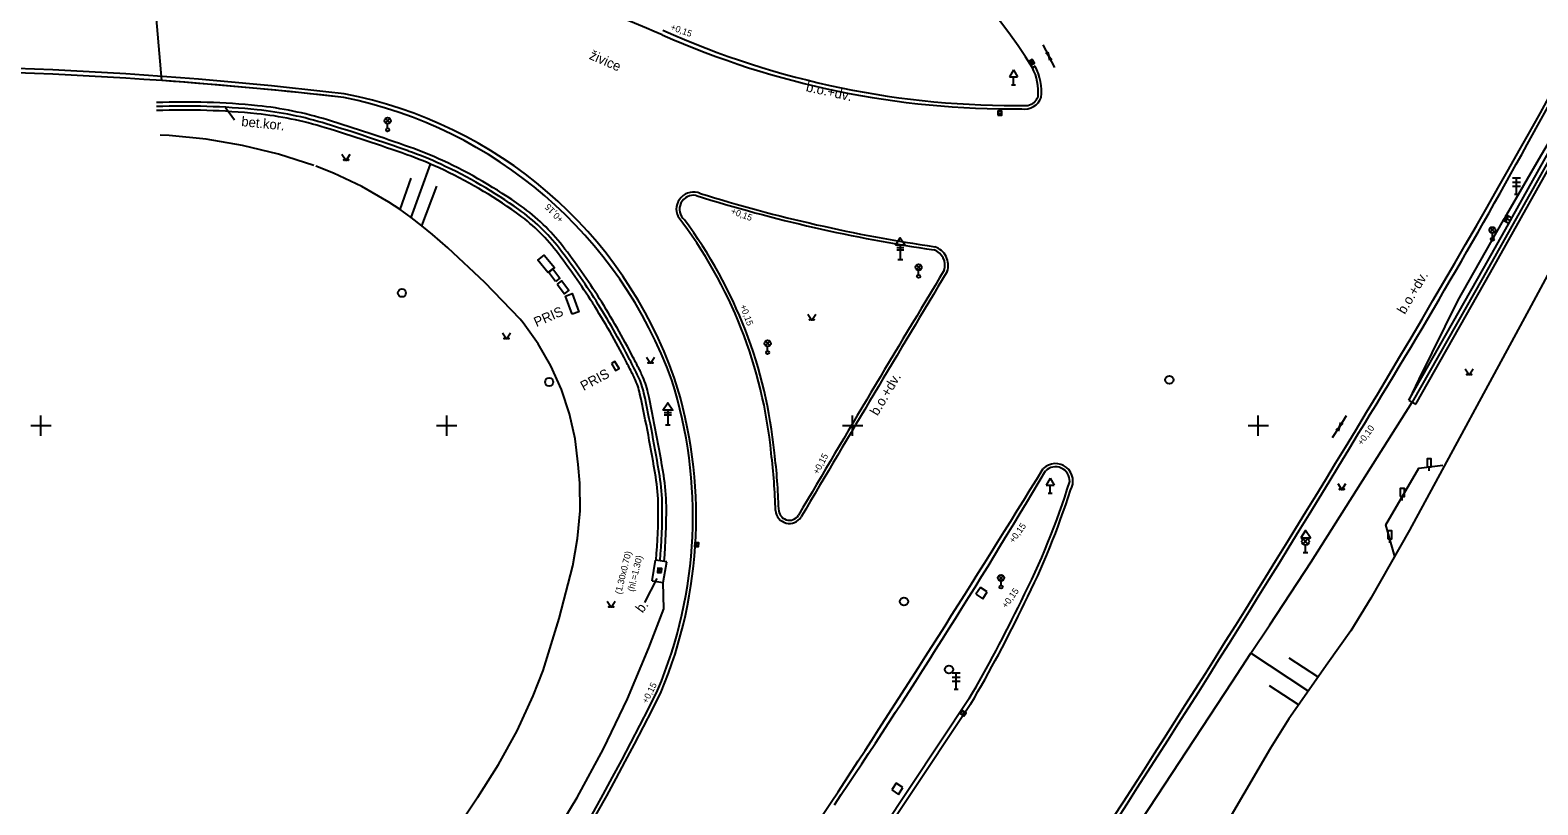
# Model space of a CAD drawing. Extents: x -599151 to -598424, y -1163476 to -1161924.
# Drawn here: x -598975.7 to -598882.8, y -1163223.4 to -1163175.6 of the extents above; entities that cross this region are included whole.
import ezdxf

# ---------------------------------------------------------------- set-up
doc = ezdxf.new("R2010")
doc.units = 0
for name, color, linetype in [('Vrstva 14', 7, 'Continuous'), ('Vrstva 15', 7, 'Continuous'), ('Vrstva 19', 7, 'Continuous'), ('Vrstva 23', 7, 'Continuous'), ('Vrstva 25', 7, 'Continuous'), ('Vrstva 29', 7, 'Continuous'), ('Vrstva 41', 7, 'Continuous'), ('Vrstva 44', 7, 'Continuous'), ('Vrstva 49', 7, 'Continuous'), ('Vrstva 50', 7, 'Continuous'), ('Vrstva 62', 7, 'Continuous'), ('Vrstva 63', 7, 'Continuous'), ('Vrstva 7', 7, 'Continuous')]:
    doc.layers.add(name, color=color, linetype=linetype)

msp = doc.modelspace()

# ---------------------------------------------------------------- linework, layer by layer
at = {"layer": 'Vrstva 14'}
for points in [[(-598956.452, -1163183.287), (-598956.202, -1163183.662), (-598955.952, -1163183.287)], [(-598927.763, -1163193.13), (-598927.513, -1163193.505), (-598927.263, -1163193.13)], [(-598946.569, -1163194.283), (-598946.319, -1163194.658), (-598946.069, -1163194.283)], [(-598937.693, -1163195.792), (-598937.443, -1163196.167), (-598937.193, -1163195.792)], [(-598887.257, -1163196.503), (-598887.007, -1163196.878), (-598886.757, -1163196.503)], [(-598895.103, -1163203.577), (-598894.853, -1163203.952), (-598894.603, -1163203.577)], [(-598940.125, -1163210.824), (-598939.875, -1163211.199), (-598939.625, -1163210.824)]]:
    msp.add_lwpolyline(points, dxfattribs=at)
for centre in [(-598956.327, -1163183.637), (-598956.077, -1163183.637), (-598927.638, -1163193.48), (-598927.388, -1163193.48), (-598946.444, -1163194.633), (-598946.194, -1163194.633), (-598937.568, -1163196.142), (-598937.318, -1163196.142), (-598887.132, -1163196.853), (-598886.882, -1163196.853), (-598894.978, -1163203.927), (-598894.728, -1163203.927), (-598940, -1163211.174), (-598939.75, -1163211.174)]:
    msp.add_circle(centre, 0.025, dxfattribs=at)
at = {"layer": 'Vrstva 15'}
for p, q in [((-598889.482, -1163202.799), (-598889.482, -1163202.549)), ((-598891.13, -1163204.621), (-598891.13, -1163204.371)), ((-598891.906, -1163207.233), (-598891.906, -1163206.983))]:
    msp.add_line(p, q, dxfattribs=at)
for points in [[(-598889.607, -1163202.549), (-598889.357, -1163202.549), (-598889.357, -1163202.049), (-598889.607, -1163202.049)], [(-598891.255, -1163204.371), (-598891.005, -1163204.371), (-598891.005, -1163203.871), (-598891.255, -1163203.871)], [(-598892.031, -1163206.983), (-598891.781, -1163206.983), (-598891.781, -1163206.483), (-598892.031, -1163206.483)]]:
    msp.add_lwpolyline(points, close=True, dxfattribs=at)
at = {"layer": 'Vrstva 19'}
for p, q in [((-598915.08, -1163178.077), (-598915.33, -1163178.51)), ((-598915.08, -1163178.077), (-598914.83, -1163178.51)), ((-598915.33, -1163178.51), (-598914.83, -1163178.51)), ((-598915.205, -1163179.01), (-598914.955, -1163179.01)), ((-598915.08, -1163179.01), (-598915.08, -1163178.51)), ((-598883.85, -1163184.75), (-598884.35, -1163184.75)), ((-598884.35, -1163185), (-598883.85, -1163185)), ((-598884.35, -1163185.25), (-598883.85, -1163185.25)), ((-598884.1, -1163185.75), (-598884.1, -1163184.75)), ((-598884.225, -1163185.75), (-598883.975, -1163185.75)), ((-598912.82, -1163203.237), (-598913.07, -1163203.67)), ((-598912.82, -1163203.237), (-598912.57, -1163203.67)), ((-598913.07, -1163203.67), (-598912.57, -1163203.67)), ((-598912.945, -1163204.17), (-598912.695, -1163204.17)), ((-598912.82, -1163204.17), (-598912.82, -1163203.67)), ((-598918.36, -1163215.25), (-598918.86, -1163215.25)), ((-598918.61, -1163216.25), (-598918.61, -1163215.25)), ((-598918.86, -1163215.5), (-598918.36, -1163215.5)), ((-598918.86, -1163215.75), (-598918.36, -1163215.75)), ((-598918.735, -1163216.25), (-598918.485, -1163216.25))]:
    msp.add_line(p, q, dxfattribs=at)
at = {"layer": 'Vrstva 23'}
for p, q in [((-598917.118, -1163209.973), (-598917.397, -1163210.388)), ((-598917.397, -1163210.388), (-598916.982, -1163210.667)), ((-598916.703, -1163210.252), (-598917.118, -1163209.973)), ((-598916.982, -1163210.667), (-598916.703, -1163210.252)), ((-598922.31, -1163222.033), (-598922.587, -1163222.45)), ((-598922.587, -1163222.45), (-598922.17, -1163222.727)), ((-598921.893, -1163222.31), (-598922.31, -1163222.033)), ((-598922.17, -1163222.727), (-598921.893, -1163222.31))]:
    msp.add_line(p, q, dxfattribs=at)
at = {"layer": 'Vrstva 25'}
for p, q in [((-598914.032, -1163177.512), (-598913.908, -1163177.728)), ((-598916.045, -1163180.752), (-598915.795, -1163180.748)), ((-598934.608, -1163207.465), (-598934.592, -1163207.215)), ((-598936.888, -1163209.055), (-598936.872, -1163208.805)), ((-598918.239, -1163217.834), (-598918.101, -1163217.626))]:
    msp.add_line(p, q, dxfattribs=at)
for points in [[(-598914.141, -1163177.574), (-598914.016, -1163177.791), (-598913.799, -1163177.666), (-598913.924, -1163177.449)], [(-598916.043, -1163180.877), (-598915.793, -1163180.873), (-598915.797, -1163180.623), (-598916.047, -1163180.627)], [(-598934.484, -1163207.473), (-598934.467, -1163207.224), (-598934.716, -1163207.207), (-598934.733, -1163207.456)], [(-598936.764, -1163209.063), (-598936.747, -1163208.814), (-598936.996, -1163208.797), (-598937.013, -1163209.046)], [(-598918.135, -1163217.903), (-598917.997, -1163217.695), (-598918.205, -1163217.557), (-598918.343, -1163217.765)]]:
    msp.add_lwpolyline(points, close=True, dxfattribs=at)
for centre in [(-598952.76, -1163191.83), (-598943.69, -1163197.32), (-598905.48, -1163197.18), (-598921.83, -1163210.84), (-598919.06, -1163215.03)]:
    msp.add_circle(centre, 0.25, dxfattribs=at)
at = {"layer": 'Vrstva 29'}
for p, q in [((-598953.772, -1163181.349), (-598953.508, -1163181.085)), ((-598953.504, -1163181.348), (-598953.768, -1163181.083)), ((-598953.64, -1163181.68), (-598953.64, -1163181.405)), ((-598885.712, -1163188.089), (-598885.448, -1163187.825)), ((-598885.444, -1163188.088), (-598885.708, -1163187.823)), ((-598885.58, -1163188.42), (-598885.58, -1163188.145)), ((-598921.062, -1163190.379), (-598920.798, -1163190.115)), ((-598920.794, -1163190.378), (-598921.058, -1163190.113)), ((-598920.93, -1163190.71), (-598920.93, -1163190.435)), ((-598930.362, -1163195.069), (-598930.098, -1163194.805)), ((-598930.094, -1163195.068), (-598930.358, -1163194.803)), ((-598930.23, -1163195.4), (-598930.23, -1163195.125)), ((-598915.982, -1163209.519), (-598915.718, -1163209.255)), ((-598915.714, -1163209.518), (-598915.978, -1163209.253)), ((-598915.85, -1163209.85), (-598915.85, -1163209.575))]:
    msp.add_line(p, q, dxfattribs=at)
for points in [[(-598943.748, -1163190.586), (-598944.38, -1163189.81), (-598943.992, -1163189.494), (-598943.36, -1163190.27)], [(-598943.305, -1163191.121), (-598943.733, -1163190.546), (-598943.47, -1163190.351), (-598943.042, -1163190.926)], [(-598943.186, -1163191.281), (-598942.743, -1163191.877), (-598942.48, -1163191.681), (-598942.923, -1163191.085)], [(-598942.279, -1163193.144), (-598942.689, -1163192.024), (-598942.27, -1163191.871), (-598941.86, -1163192.991)], [(-598939.855, -1163196.179), (-598939.6, -1163196.609), (-598939.385, -1163196.481), (-598939.64, -1163196.051)]]:
    msp.add_lwpolyline(points, close=True, dxfattribs=at)
for centre, radius in [((-598953.64, -1163181.218), 0.188), ((-598953.64, -1163181.78), 0.1), ((-598885.58, -1163187.958), 0.188), ((-598885.58, -1163188.52), 0.1), ((-598920.93, -1163190.248), 0.188), ((-598920.93, -1163190.81), 0.1), ((-598930.23, -1163194.938), 0.188), ((-598930.23, -1163195.5), 0.1), ((-598915.85, -1163209.387), 0.188), ((-598915.85, -1163209.95), 0.1)]:
    msp.add_circle(centre, radius, dxfattribs=at)
at = {"layer": 'Vrstva 41'}
for points in [[(-598860.74, -1163142.45), (-598862.47, -1163146.02), (-598866.78, -1163154.95), (-598871.49, -1163164.01), (-598875.071, -1163170.982), (-598876.19, -1163173.07), (-598881.31, -1163182.23), (-598886.17, -1163190.91), (-598890.52, -1163198.56)], [(-598871.534, -1163162.726), (-598873.454, -1163166.836), (-598874.844, -1163169.688), (-598876.517, -1163172.895), (-598877.633, -1163174.986), (-598879.324, -1163177.864), (-598882.626, -1163183.413), (-598884.716, -1163187.009)], [(-598868.964, -1163164.861), (-598872.292, -1163172.181), (-598875.896, -1163179.066), (-598883.188, -1163192.607), (-598890.693, -1163206.441), (-598893.069, -1163210.629), (-598894.293, -1163212.647), (-598895.708, -1163214.65)], [(-598958.19, -1163183.977), (-598960.363, -1163183.282), (-598962.579, -1163182.741), (-598964.827, -1163182.357), (-598967.097, -1163182.131), (-598967.65, -1163182.1)], [(-598953.558, -1163186.239), (-598955.226, -1163185.275), (-598956.969, -1163184.453), (-598958.063, -1163184.023)], [(-598952.192, -1163187.177), (-598950.993, -1163183.89)], [(-598952.869, -1163186.694), (-598952.186, -1163184.764)], [(-598951.525, -1163187.689), (-598950.611, -1163185.244)], [(-598952.869, -1163186.694), (-598953.558, -1163186.239)], [(-598952.192, -1163187.177), (-598952.869, -1163186.694)], [(-598951.525, -1163187.689), (-598952.192, -1163187.177)], [(-598884.911, -1163187.35), (-598886.752, -1163190.574), (-598887.7, -1163192.277), (-598890.11, -1163197.14), (-598890.737, -1163198.437)], [(-598884.862, -1163187.265), (-598884.911, -1163187.35)], [(-598884.911, -1163187.35), (-598884.569, -1163187.542)], [(-598884.814, -1163187.18), (-598884.862, -1163187.265)], [(-598884.862, -1163187.265), (-598884.692, -1163187.36)], [(-598884.765, -1163187.095), (-598884.814, -1163187.18)], [(-598884.814, -1163187.18), (-598884.473, -1163187.371)], [(-598884.716, -1163187.009), (-598884.765, -1163187.095)], [(-598884.765, -1163187.095), (-598884.595, -1163187.19)], [(-598884.716, -1163187.009), (-598884.377, -1163187.199)], [(-598950.87, -1163188.231), (-598951.525, -1163187.689)], [(-598948.093, -1163222.895), (-598946.811, -1163220.893), (-598945.667, -1163218.809), (-598944.666, -1163216.652), (-598944.051, -1163215.102), (-598943.066, -1163211.887), (-598942.24, -1163208.65), (-598941.934, -1163206.965), (-598941.787, -1163205.259), (-598941.8, -1163203.547), (-598941.898, -1163202.399), (-598942.085, -1163200.826), (-598942.43, -1163199.281), (-598942.929, -1163197.777), (-598943.578, -1163196.332), (-598944.368, -1163194.96), (-598945.293, -1163193.674), (-598945.473, -1163193.453), (-598947.645, -1163191.196), (-598949.929, -1163189.053), (-598950.87, -1163188.231)], [(-598899.301, -1163212.279), (-598896.747, -1163208.396), (-598890.52, -1163198.561)], [(-598957.077, -1163245.352), (-598954.899, -1163242.419), (-598951.443, -1163237.628), (-598948.118, -1163232.746), (-598944.927, -1163227.775), (-598943.729, -1163225.829), (-598941.97, -1163222.909), (-598940.349, -1163219.91), (-598938.871, -1163216.838), (-598937.539, -1163213.7), (-598936.629, -1163211.285), (-598936.66, -1163209.681)], [(-598900.453, -1163214.03), (-598899.301, -1163212.279)], [(-598901.605, -1163215.781), (-598900.453, -1163214.03)], [(-598896.952, -1163216.336), (-598900.453, -1163214.03)], [(-598896.34, -1163215.485), (-598898.095, -1163214.328)], [(-598895.708, -1163214.65), (-598898.121, -1163218.067)], [(-598934.287, -1163264.66), (-598930.315, -1163258.944), (-598918.768, -1163242.608), (-598908.111, -1163225.673), (-598901.605, -1163215.781)], [(-598897.545, -1163217.195), (-598899.309, -1163216.037)], [(-598898.121, -1163218.067), (-598899.25, -1163219.88), (-598904.189, -1163228.309), (-598906.11, -1163231.527), (-598909.79, -1163237.461)], [(-598948.093, -1163222.895), (-598950.408, -1163226.37), (-598953.659, -1163230.894), (-598956.188, -1163234.279), (-598959.689, -1163239.199), (-598961.585, -1163242.031)]]:
    msp.add_lwpolyline(points, dxfattribs=at)
for centre, radius, start, end in [((-598966.176, -1163224.983), 44.662, 84.21349, 92.18628), ((-598963.872, -1163202.248), 21.811, 72.79527, 84.21349), ((-598998.003, -1163312.474), 137.201, 70.5727, 72.79527), ((-598998.003, -1163312.474), 137.201, 70.5727, 72.79527), ((-598959.938, -1163204.55), 22.76, 65.11435, 70.5727), ((-598963.103, -1163211.371), 30.279, 54.60383, 65.11435), ((-598952.373, -1163196.271), 11.756, 37.69923, 54.60383), ((-598976.674, -1163215.051), 42.467, 32.35739, 37.69923), ((-598980.414, -1163217.422), 46.896, 27.27417, 32.35739), ((-599025.168, -1163240.495), 97.248, 26.58123, 27.27417), ((-598942.374, -1163198.979), 4.629, 12.15219, 25.58641), ((-599042.066, -1163220.446), 106.606, 9.35895, 12.15219), ((-598948.7, -1163205.058), 11.98, 0.45562, 9.35895), ((-598971.735, -1163205.241), 35.017, 354.93357, 0.45562)]:
    msp.add_arc(centre, radius, start, end, dxfattribs=at)
at = {"layer": 'Vrstva 44'}
for p, q in [((-598922.28, -1163189.03), (-598921.832, -1163189.03)), ((-598922.28, -1163189.18), (-598921.837, -1163189.18)), ((-598922.06, -1163188.88), (-598922.06, -1163189.78)), ((-598922.21, -1163189.78), (-598921.91, -1163189.78)), ((-598936.6, -1163199.2), (-598936.152, -1163199.2)), ((-598936.6, -1163199.35), (-598936.157, -1163199.35)), ((-598936.38, -1163199.05), (-598936.38, -1163199.95)), ((-598936.53, -1163199.95), (-598936.23, -1163199.95)), ((-598896.94, -1163206.97), (-598897.24, -1163207.314)), ((-598897.24, -1163206.97), (-598896.94, -1163207.314)), ((-598897.24, -1163207.82), (-598896.94, -1163207.82)), ((-598897.09, -1163207.82), (-598897.09, -1163207.37))]:
    msp.add_line(p, q, dxfattribs=at)
for points in [[(-598922.36, -1163188.885), (-598922.06, -1163188.43), (-598921.76, -1163188.885)], [(-598936.68, -1163199.055), (-598936.38, -1163198.6), (-598936.08, -1163199.055)]]:
    msp.add_lwpolyline(points, close=True, dxfattribs=at)
for points in [[(-598891.6, -1163208.061), (-598892.15, -1163206.121), (-598890.11, -1163202.621), (-598888.63, -1163202.451)], [(-598897.39, -1163206.914), (-598896.79, -1163206.914), (-598897.09, -1163206.464), (-598897.39, -1163206.914)]]:
    msp.add_lwpolyline(points, dxfattribs=at)
msp.add_circle((-598897.09, -1163207.142), 0.228, dxfattribs=at)
at = {"layer": 'Vrstva 49'}
for p, q in [((-598913.266, -1163176.538), (-598912.903, -1163177.242)), ((-598912.903, -1163177.242), (-598913.093, -1163177.036)), ((-598912.964, -1163176.969), (-598912.903, -1163177.242)), ((-598912.541, -1163177.946), (-598912.903, -1163177.242)), ((-598912.844, -1163177.514), (-598912.903, -1163177.242)), ((-598912.903, -1163177.242), (-598912.715, -1163177.449)), ((-598963.62, -1163180.4), (-598963.078, -1163181.157)), ((-598894.586, -1163199.399), (-598895.004, -1163200.072)), ((-598895.423, -1163200.744), (-598895.004, -1163200.072)), ((-598895.207, -1163200.263), (-598895.004, -1163200.072)), ((-598895.004, -1163200.072), (-598895.084, -1163200.34)), ((-598895.004, -1163200.072), (-598894.924, -1163199.804)), ((-598894.801, -1163199.881), (-598895.004, -1163200.072))]:
    msp.add_line(p, q, dxfattribs=at)
msp.add_lwpolyline([(-598937.065, -1163209.42), (-598937.819, -1163210.896)], dxfattribs=at)
at = {"layer": 'Vrstva 62'}
for p, q in [((-598975, -1163200.625), (-598975, -1163199.375)), ((-598950, -1163200.625), (-598950, -1163199.375)), ((-598925, -1163200.625), (-598925, -1163199.375)), ((-598900, -1163200.625), (-598900, -1163199.375)), ((-598975.625, -1163200), (-598974.375, -1163200)), ((-598950.625, -1163200), (-598949.375, -1163200)), ((-598925.625, -1163200), (-598924.375, -1163200)), ((-598900.625, -1163200), (-598899.375, -1163200))]:
    msp.add_line(p, q, dxfattribs=at)
at = {"layer": 'Vrstva 63'}
for points in [[(-598967.543, -1163178.748), (-598968.28, -1163170.41)], [(-598917.814, -1163216.827), (-598934.06, -1163241.28), (-598944.72, -1163256.94), (-598957.46, -1163274.82), (-598968.32, -1163289.56), (-598974.06, -1163297.12)]]:
    msp.add_lwpolyline(points, dxfattribs=at)
for centre, radius, start, end in [((-598941.11, -1163194.732), 31.947, 31.6672, 77.43438), ((-598914.982, -1163127.244), 53.042, 245.84104, 270.84426), ((-598916.725, -1163179.436), 3.169, 354.49349, 27.75471), ((-598986.233, -1163440.359), 262.278, 83.45562, 85.91373), ((-598961.729, -1163206.475), 27.224, 19.89721, 78.58344), ((-598914.387, -1163179.424), 0.876, 282.33457, 338.86802), ((-599249.024, -1162981.16), 417.452, 328.30794, 331.32194), ((-598934.796, -1163186.673), 0.859, 78.84888, 229.86889), ((-598906.237, -1163095.371), 94.811, 252.57404, 261.66534), ((-598958.355, -1163204.456), 28.679, 5.55384, 36.66559), ((-598920.308, -1163190.129), 1.004, 342.54461, 70.95248), ((-597750.226, -1163895.931), 1365.497, 148.891378, 149.62855), ((-598962.51, -1163205.576), 27.675, 337.1336, 17.59603), ((-599658.78, -1162738.442), 893.663, 326.465964, 328.868431), ((-598965.955, -1163206.136), 36.419, 1.56697, 7.02779), ((-599283.752, -1162982.854), 430.985, 326.07822, 329.31447), ((-598912.496, -1163203.422), 0.878, 357.9528, 134.58623), ((-598956.351, -1163189.583), 46.833, 333.0068, 342.77246), ((-598928.887, -1163205.168), 0.664, 177.54157, 327.00172), ((-598993.563, -1163172.571), 87.73, 329.70485, 334.13753), ((-599106.143, -1163131.806), 189.077, 321.77804, 333.44649)]:
    msp.add_arc(centre, radius, start, end, dxfattribs=at)
at = {"layer": 'Vrstva 7'}
for p, q in [((-598913.743, -1163177.867), (-598913.92, -1163177.96)), ((-598890.737, -1163198.437), (-598890.303, -1163198.684)), ((-598937.351, -1163209.567), (-598937.141, -1163208.287)), ((-598936.45, -1163208.401), (-598937.141, -1163208.287)), ((-598936.66, -1163209.681), (-598936.45, -1163208.401)), ((-598937.351, -1163209.567), (-598936.66, -1163209.681))]:
    msp.add_line(p, q, dxfattribs=at)
for points in [[(-598890.737, -1163198.437), (-598886.128, -1163190.328), (-598884.593, -1163187.585), (-598884.349, -1163187.15), (-598876.04, -1163172.302), (-598871.253, -1163163.046), (-598871.016, -1163162.588), (-598866.573, -1163153.999), (-598863.949, -1163148.545), (-598863.607, -1163147.833), (-598860.965, -1163142.342)], [(-598890.303, -1163198.684), (-598885.692, -1163190.573), (-598875.6, -1163172.539), (-598866.126, -1163154.222), (-598860.515, -1163142.559)], [(-598917.814, -1163216.827), (-598934.06, -1163241.28), (-598944.72, -1163256.94), (-598957.46, -1163274.82), (-598968.32, -1163289.56), (-598974.06, -1163297.12)], [(-598917.713, -1163217.151), (-598933.85, -1163241.41), (-598944.55, -1163257.09), (-598957.27, -1163274.98), (-598968.13, -1163289.67), (-598973.896, -1163297.234)], [(-598974.485, -1163290.767), (-598971.79, -1163287.12), (-598960.37, -1163271.72), (-598948.01, -1163254.7), (-598937.07, -1163239.3), (-598926.31, -1163223.2)]]:
    msp.add_lwpolyline(points, dxfattribs=at)
for centre, radius, start, end in [((-599386.517, -1162899.53), 577.281, 330.762706, 334.813631), ((-599422.302, -1162879.86), 617.881, 328.758636, 332.714644), ((-598941.11, -1163194.732), 31.947, 31.6672, 77.43437), ((-598971.154, -1163256.167), 87.319, 66.78182, 77.84413), ((-598915.184, -1163127.389), 53.099, 246.06096, 270.66041), ((-598914.982, -1163127.244), 53.042, 245.84104, 270.84426), ((-598985.974, -1163430.067), 252.247, 83.24878, 91.43483), ((-598986.233, -1163440.359), 262.278, 83.45562, 91.31465), ((-598916.725, -1163179.436), 3.169, 354.49349, 27.75472), ((-598916.725, -1163179.436), 3.369, 354.04419, 27.75472), ((-598966.176, -1163224.983), 44.915, 84.21349, 92.18628), ((-598961.729, -1163206.475), 27.224, 19.89721, 78.58343), ((-598961.347, -1163205.996), 26.9, 19.29772, 79.22864), ((-598914.387, -1163179.424), 1.076, 260.09561, 340.38024), ((-598914.387, -1163179.424), 0.876, 282.33457, 338.86802), ((-598966.176, -1163224.983), 44.415, 84.21349, 92.18628), ((-598963.872, -1163202.248), 21.564, 72.79527, 84.21349), ((-598963.872, -1163202.248), 22.064, 72.79527, 84.21349), ((-598998.003, -1163312.475), 136.954, 70.5727, 72.79527), ((-598998.003, -1163312.475), 137.454, 70.5727, 72.79527), ((-599249.024, -1162981.16), 417.452, 328.30794, 331.32194), ((-598959.939, -1163204.55), 23.013, 65.11435, 70.5727), ((-598959.939, -1163204.55), 22.513, 65.11435, 70.5727), ((-598963.103, -1163211.37), 30.532, 54.60383, 65.11435), ((-598963.103, -1163211.37), 30.032, 54.60383, 65.11435), ((-598934.796, -1163186.673), 1.059, 67.03573, 205.543), ((-598952.373, -1163196.271), 12.008, 37.69923, 54.60383), ((-598934.796, -1163186.673), 0.859, 78.84904, 229.86895), ((-598906.237, -1163095.371), 94.811, 252.57404, 261.66534), ((-598906.237, -1163095.371), 94.611, 252.69282, 261.67618), ((-598952.373, -1163196.271), 11.508, 37.69923, 54.60383), ((-598958.355, -1163204.456), 28.479, 5.54867, 37.47157), ((-598958.355, -1163204.456), 28.679, 5.55384, 36.66559), ((-598976.673, -1163215.051), 42.22, 32.35739, 37.69923), ((-598976.673, -1163215.051), 42.72, 32.35739, 37.69923), ((-598920.308, -1163190.129), 1.004, 342.54383, 70.95238), ((-598920.308, -1163190.129), 1.204, 341.35331, 71.88552), ((-597750.226, -1163895.931), 1365.497, 148.891381, 149.628553), ((-597750.226, -1163895.931), 1365.297, 148.890422, 149.628731), ((-598980.414, -1163217.421), 46.648, 27.27417, 32.35739), ((-598980.414, -1163217.421), 47.148, 27.27417, 32.35739), ((-599025.168, -1163240.495), 97.5, 26.7829, 27.27417), ((-599025.168, -1163240.495), 97, 26.7829, 27.27417), ((-598952.987, -1163204.061), 16.145, 25.58641, 26.7829), ((-598952.987, -1163204.061), 16.645, 25.58641, 26.7829), ((-598942.375, -1163198.98), 4.379, 12.15219, 25.58641), ((-598942.375, -1163198.98), 4.879, 12.15219, 25.58641), ((-598962.51, -1163205.576), 27.675, 337.1336, 17.59603), ((-598962.645, -1163205.627), 28.014, 337.36147, 17.70863), ((-599042.066, -1163220.446), 106.355, 9.35895, 12.15219), ((-599042.066, -1163220.446), 106.855, 9.35895, 12.15219), ((-599662.532, -1162735.648), 898.07, 326.448422, 328.8412), ((-599658.78, -1162738.442), 893.663, 326.465964, 328.868431), ((-598965.955, -1163206.136), 36.219, 1.41259, 7.03187), ((-598965.955, -1163206.136), 36.419, 1.56697, 7.0278), ((-598912.496, -1163203.422), 1.078, 328.50604, 134.56351), ((-598948.7, -1163205.059), 11.73, 0.45562, 9.35895), ((-598948.7, -1163205.059), 12.23, 0.45562, 9.35895), ((-599634.022, -1162759.005), 846.364, 326.73875, 328.386794), ((-599283.752, -1162982.854), 430.985, 326.07823, 329.31447), ((-598912.496, -1163203.422), 0.878, 357.9528, 134.58623), ((-598956.351, -1163189.583), 46.833, 333.0068, 342.77246), ((-598956.451, -1163189.853), 47.046, 333.35722, 342.51932), ((-598971.735, -1163205.242), 34.766, 354.96463, 0.45562), ((-598971.735, -1163205.242), 35.266, 354.90381, 0.45562), ((-598928.887, -1163205.168), 0.664, 177.54144, 327.0033), ((-598928.887, -1163205.168), 0.864, 184.95104, 327.32724), ((-598993.563, -1163172.571), 87.73, 329.70485, 334.13753), ((-598993.555, -1163172.649), 87.934, 329.59726, 334.17916), ((-599106.143, -1163131.806), 189.077, 321.77804, 333.44648), ((-599104.112, -1163132.89), 187.009, 321.66636, 333.4735)]:
    msp.add_arc(centre, radius, start, end, dxfattribs=at)

# ---------------------------------------------------------------- texts
at = {"layer": 'Vrstva 49'}
for s, rotation, p in [('živice', 336.57495, (-598941.268, -1163177.397)), ('b.o.+dv.', 347.44866, (-598927.906, -1163179.398)), ('bet.kor.', 354.13471, (-598962.674, -1163181.546)), ('b.o.+dv.', 59.31157, (-598890.977, -1163193.187)), ('PRIS', 23.65606, (-598944.473, -1163193.94)), ('PRIS', 28.18789, (-598941.565, -1163197.88)), ('b.o.+dv.', 59.31157, (-598923.456, -1163199.441)), ('b.', 53.69327, (-598937.939, -1163211.589))]:
    msp.add_text(s, height=0.6, rotation=rotation, dxfattribs=at).set_placement(p)
at = {"layer": 'Vrstva 50'}
for s, rotation, p in [('+0,15', 340.06587, (-598936.249, -1163175.609)), ('+0,15', 133.69901, (-598942.775, -1163187.273)), ('+0,15', 339.74681, (-598932.534, -1163186.941)), ('+0,15', 290.34934, (-598931.944, -1163192.626)), ('+0,10', 54.30175, (-598893.612, -1163201.255)), ('+0,15', 61.70827, (-598927.12, -1163203.051)), ('+0,15', 54.30175, (-598915.069, -1163207.286)), ('(1.30x0.70)', 76.17375, (-598939.257, -1163210.419)), ('(hl.=1.30)', 76.17375, (-598938.48, -1163210.262)), ('+0,15', 54.30175, (-598915.515, -1163211.292)), ('+0,15', 63.49004, (-598937.643, -1163217.166))]:
    msp.add_text(s, height=0.4, rotation=rotation, dxfattribs=at).set_placement(p)

doc.saveas('drawing.dxf')
